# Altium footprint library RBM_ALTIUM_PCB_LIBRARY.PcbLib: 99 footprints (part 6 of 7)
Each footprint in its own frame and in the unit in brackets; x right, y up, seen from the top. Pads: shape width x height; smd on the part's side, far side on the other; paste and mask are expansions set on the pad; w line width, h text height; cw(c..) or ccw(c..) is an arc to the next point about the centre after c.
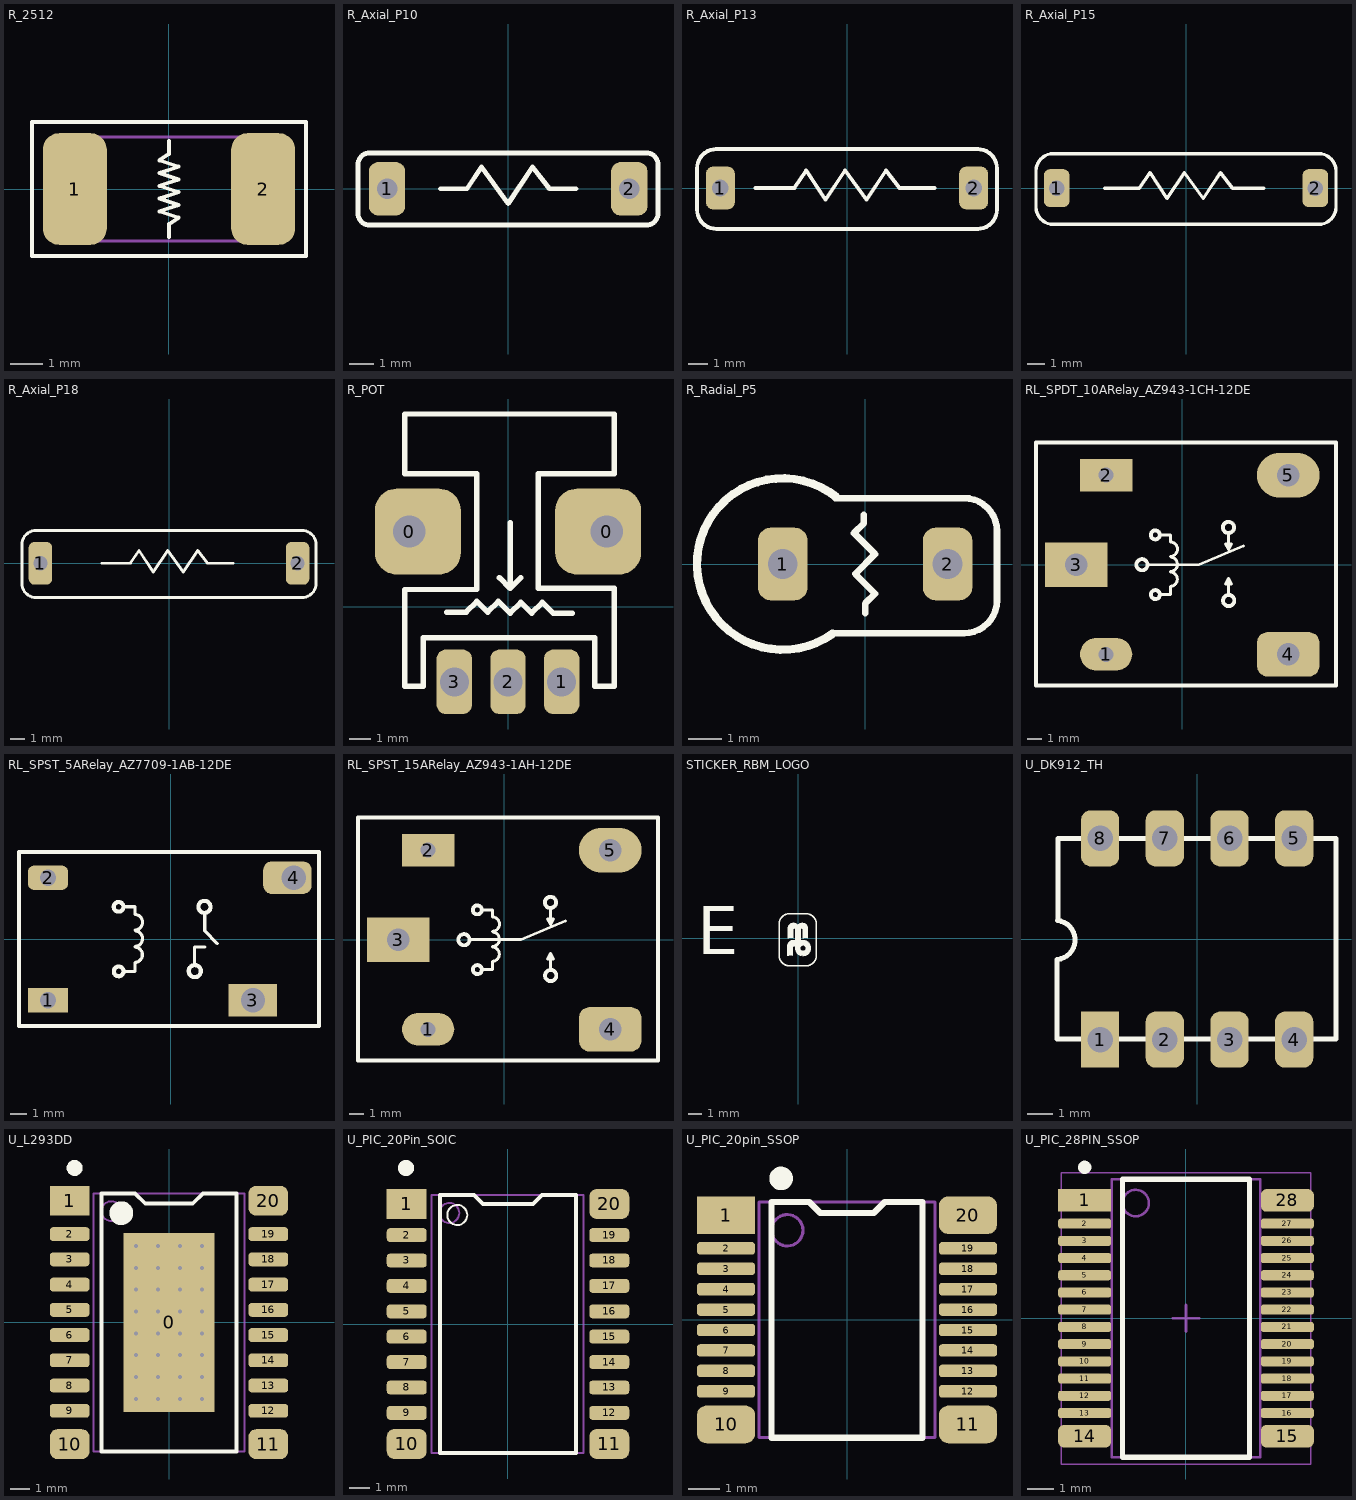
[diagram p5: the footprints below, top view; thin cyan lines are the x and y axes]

## R_2512 [mm] "Chip Resistor, 2-Leads, Body 6.35x3.10mm, IPC Medium Density"
height 0.65
pads (2):
  rrect50% 2x3.5 smd: 1(-2.95,0) 2(2.95,0)
Top Overlay:
  lines w0.125: 0,-1.5 0,-1.1 0.3,-0.9 -0.3,-0.7 0.3,-0.5 -0.3,-0.3 0.3,-0.1 -0.3,0.1 0.3,0.3 -0.3,0.5 0.3,0.7 -0.3,0.9 0,1.1 0,1.5 ; -4.3,-2.1 4.3,-2.1 4.3,2.1 -4.3,2.1 -4.3,-2.1
Mechanical 13:
  lines w0.1: -3.275,-1.625 3.275,-1.625 3.275,1.625 -3.275,1.625 -3.275,-1.625
3D body "R_2512.step": height 0.65, standoff 0, extent -3.275,-1.625 3.275,1.625

## R_Axial_P10 [mm] "Resistors 7mm Length"
pads (2):
  rrect50% 1.5x2.2 hole 0.85: 1(-5,0) 2(5,0)
Top Overlay:
  lines w0.2: -2.8,0 -1.7,0 -1.1,0.9 0,-0.6 1,0.9 1.7,0 2.8,0 ; -6.2,-1.017 ccw(c-5.717,-1.017) -5.717,-1.5 5.7,-1.5 ccw(c5.7,-1.017) 6.183,-1.017 6.183,1 ccw(c5.7,1) 5.7,1.483 -5.717,1.483 ccw(c-5.717,1) -6.2,1 -6.2,-1.017
3D body "User Library-Res40-Axial 0_25W-2_2R.step": height 2.41, standoff -2, extent -5.38,-1.2 5.38,1.2

## R_Axial_P13 [mm] "Resistors 10.5mm Length"
pads (2):
  rrect50% 1.5x2.2 hole 0.85: 1(-6.5,0) 2(6.5,0)
Top Overlay:
  lines w0.2: -6.725,2 6.725,2 ; -6.7,2 ccw(c-6.7,1) -7.7,1 -7.7,-1.1 ccw(c-6.7,-1.1) -6.7,-2.1 6.725,-2.1 ; -4.7,0 -2.7,0 -2.1,0.9 -1.1,-0.6 -0.1,0.9 1,-0.6 2,0.9 2.7,0 4.5,0 ; 6.7,-2.1 ccw(c6.7,-1.1) 7.7,-1.1 7.7,1 ccw(c6.7,1) 6.7,2
3D body "User Library-Res50-Axial 0_5W-2_2K.step": height 5.87, standoff -3.5, extent -6.725,-1.875 6.725,1.875

## R_Axial_P15 [mm] "Resistors 12mm Length"
pads (2):
  rrect50% 1.5x2.2 hole 0.9: 1(-7.5,0) 2(7.5,0)
Top Overlay:
  lines w0.2: -4.7,0 -2.7,0 -2.1,0.9 -1.1,-0.6 -0.1,0.9 1,-0.6 2,0.9 2.7,0 4.5,0 ; -8.7,-1.1 ccw(c-7.7,-1.1) -7.7,-2.1 7.7,-2.1 ccw(c7.7,-1.1) 8.7,-1.1 8.7,1 ccw(c7.7,1) 7.7,2 -7.7,2 ccw(c-7.7,1) -8.7,1 -8.7,-1.1
3D body "User Library-Res50-Axial 0_5W-2_2K.step": height 5.87, standoff -3.5, extent -6.725,-1.875 6.725,1.875

## R_Axial_P18 [mm] "220 ohm 2W 5%"
pads (2):
  rrect50% 1.65x3 hole 1: 1(-9,0) 2(9,0)
Top Overlay:
  lines w0.2: -4.7,0 -2.7,0 -2.1,0.9 -1.1,-0.6 -0.1,0.9 1,-0.6 2,0.9 2.7,0 4.5,0 ; -10.3,-1.4 ccw(c-9.3,-1.4) -9.3,-2.4 9.3,-2.4 ccw(c9.3,-1.4) 10.3,-1.4 10.3,1.3 ccw(c9.3,1.3) 9.3,2.3 -9.3,2.3 ccw(c-9.3,1.3) -10.3,1.3 -10.3,-1.4

## R_POT [mm]
pads (5):
  rrect50% 4x4 hole 1.5 square copper offset 0.4,0: 0(-4.6,3.5)
  rrect50% 4x4 hole 1.5 square copper offset -0.4,0: 0(4.6,3.5)
  rrect50% 1.65x3 hole 1.35: 1(2.5,-3.5) 2(0,-3.5) 3(-2.5,-3.5)
Top Overlay:
  lines w0.254: -2.85,-0.25 -1.95,-0.25 -1.45,0.25 ; -0.4,1.35 0.1,0.85 ; 0.05,-0.25 -0.45,0.25 ; 0.1,3.9 0.1,0.85 ; 0.6,1.35 0.1,0.85 ; 3,-0.3 2.1,-0.3 1.6,0.2 1.1,-0.3 ; -1.45,0.25 -1.45,0.25 ; -1.45,0.25 -0.95,-0.25 -0.45,0.25 ; -0.45,0.25 -0.45,0.25 ; 0.1,-0.3 0.1,-0.3 ; 0.1,-0.3 0.6,0.2 1.1,-0.3 ; 1.1,-0.3 1.1,-0.3 ; -4.8,-3.7 -4.8,0.8 -1.45,0.8 -1.45,6.2 -4.8,6.2 -4.8,8.975 4.952,8.975 4.952,6.2 1.4,6.2 1.4,0.85 4.952,0.85 4.952,-3.7 4.05,-3.7 4.05,-1.45 -3.95,-1.45 -3.95,-3.7 -4.8,-3.7
3D body "SW3dPS-Potentiometer 250U.STEP": height 15.26, standoff -3.8, extent -4.876,-3.8 4.876,8.75

## R_Radial_P5 [mm] "All Through Hole Resistors"
pads (2):
  rrect50% 1.5x2.2 hole 0.9: 1(-2.5,0) 2(2.5,0)
Top Overlay:
  lines w0.2: -1,-2.1 3,-2.1 ccw(c3,-1.1) 4,-1.1 4,1 ccw(c3,1) 3,2 -0.9,2 ; -0.038,1.5 -0.038,1.238 -0.337,0.938 0.3,0.3 ; 0,-1.5 0,-1.2 0.3,-0.9 -0.3,-0.3 ; -0.3,-0.3 0.3,0.3 ; -0.3,-0.3 -0.3,-0.3 ; 0.3,0.3 0.3,0.3
  lines w0.254: -0.989,-2.116 cw(c-2.5,0) -0.876,2.03
3D body "Res_Radial_5mmP.STEP": height 15.25, standoff -3, extent -5,-2.5 2.75,2.5

## RL_SPDT_10ARelay_AZ943-1CH-12DE [mm]
pads (5):
  oval 3.5x2.2 hole 1: 1(-5.1,-6)
  rect 3.5x2.2 hole 1: 2(-5.1,6)
  rect 4.2x3 hole 1.5: 3(-7.1,0)
  rrect50% 4.2x3 hole 1.5: 4(7.1,-6)
  oval 4.2x3 hole 1.5: 5(7.1,6)
Top Overlay:
  circle w0.254: c-1.8,-2.001 r0.3
  circle w0.254: c-1.804,2 r0.3
  circle w0.254: c3.111,-2.4 r0.376
  circle w0.254: c3.096,2.5 r0.376
  circle w0.254: c-2.704,0 r0.376
  lines w0.2: -2.329,0 1.096,0 4.109,1.268 ; -1.429,2 -0.789,2 -0.789,1.534 ; -1.424,-2.001 -0.784,-2.001 ; -0.791,-1.444 ccw(c-0.81,-0.968) -0.789,-0.492 ; -0.79,-0.458 ccw(c-0.81,0.028) -0.747,0.511 ; -0.79,0.559 ccw(c-0.81,1.046) -0.789,1.533 ; -0.789,-1.986 -0.789,-1.477 ; 3.096,-2.039 3.096,-0.906 ; 3.111,2.139 3.111,1.006 ; 2.896,1.4 3.111,1.006 ; 2.896,1.4 3.111,1.006 ; 2.896,1.4 3.111,1.4 ; 3.096,-1.3 3.311,-1.3 ; 3.096,-1.3 3.096,-0.906 ; 3.096,-1.3 2.896,-1.3 3.096,-0.906 ; 3.096,-0.906 3.311,-1.3 ; 3.096,-0.906 3.311,-1.3 ; 3.111,1.006 3.111,1.4 ; 3.111,1.006 3.311,1.4 3.111,1.4
  lines w0.254: -9.8,8.2 -9.8,-8.1 10.3,-8.1 10.3,8.2 -9.7,8.2
3D body: height 3, standoff -4, extent -5.348,-6.249 -4.85,-5.75
3D body: height 3, standoff -4, extent -7.695,-0.599 -6.5,0.599
3D body: height 3, standoff -4, extent -5.348,5.751 -4.85,6.25
3D body: height 3, standoff -4, extent 6.505,5.401 7.7,6.599
3D body: height 3, standoff -4, extent 6.505,-6.599 7.7,-5.401
3D body: height 15, standoff 0.56, extent -9.8,-8.1 10.3,8.2

## RL_SPST_5ARelay_AZ7709-1AB-12DE [mm]
pads (4):
  rect 2.5x1.5 hole 1: 1(-7.62,-3.8)
  rrect50% 2.5x1.5 hole 1: 2(-7.62,3.8)
  rect 3x2 hole 1.5: 3(5.08,-3.8)
  rrect50% 3x2 hole 1.5 copper offset -0.4,0: 4(7.62,3.8)
Top Overlay:
  circle w0.254: c-3.244,1.993 r0.3
  circle w0.254: c-3.24,-2.008 r0.3
  circle w0.254: c1.48,-1.993 r0.376
  circle w0.254: c2.08,1.993 r0.376
  lines w0.2: -2.869,1.993 -2.229,1.993 -2.229,1.526 ; -2.865,-2.008 -2.225,-2.008 ; -2.231,-1.451 ccw(c-2.25,-0.975) -2.229,-0.499 ; -2.231,-0.466 ccw(c-2.25,0.021) -2.187,0.504 ; -2.231,0.552 ccw(c-2.25,1.039) -2.229,1.525 ; -2.229,-1.993 -2.229,-1.484 ; 1.465,-1.632 1.465,-0.499 2.095,-0.499 ; 2.095,1.631 2.095,0.499 2.88,-0.286
  lines w0.254: -9.42,-5.4 9.18,-5.4 9.18,5.4 -9.42,5.4 -9.42,-5.4
3D body: height 15.5, standoff 0.56, extent -9.42,-5.4 9.18,5.4
3D body: height 3, standoff -4, extent 7.025,3.201 8.22,4.399
3D body: height 3, standoff -4, extent -7.868,3.551 -7.37,4.05
3D body: height 3, standoff -4, extent 4.485,-4.399 5.68,-3.201
3D body: height 3, standoff -4, extent -7.868,-4.049 -7.37,-3.55

## RL_SPST_15ARelay_AZ943-1AH-12DE [mm]
pads (5):
  oval 3.5x2.2 hole 1: 1(-5.1,-6)
  rect 3.5x2.2 hole 1: 2(-5.1,6)
  rect 4.2x3 hole 1.5: 3(-7.1,0)
  rrect50% 4.2x3 hole 1.5: 4(7.1,-6)
  oval 4.2x3 hole 1.5: 5(7.1,6)
Top Overlay:
  circle w0.254: c-1.8,-2 r0.3
  circle w0.254: c-1.804,2.001 r0.3
  circle w0.254: c3.111,-2.399 r0.376
  circle w0.254: c3.096,2.501 r0.376
  circle w0.254: c-2.704,0.001 r0.376
  lines w0.2: -2.329,0.001 1.096,0.001 4.109,1.269 ; -1.429,2.001 -0.789,2.001 -0.789,1.535 cw(c-0.81,1.047) -0.79,0.56 ; -1.424,-2 -0.784,-2 ; -0.791,-1.443 ccw(c-0.81,-0.967) -0.789,-0.491 ; -0.79,-0.457 ccw(c-0.81,0.029) -0.747,0.512 ; -0.789,-1.985 -0.789,-1.476 ; 3.096,-2.038 3.096,-0.905 ; 3.111,2.14 3.111,1.007 ; 2.896,1.401 3.111,1.007 ; 2.896,1.401 3.111,1.007 ; 2.896,1.401 3.111,1.401 ; 3.096,-1.299 3.311,-1.299 ; 3.096,-1.299 3.096,-0.905 ; 3.096,-1.299 2.896,-1.299 3.096,-0.905 ; 3.096,-0.905 3.311,-1.299 ; 3.096,-0.905 3.311,-1.299 ; 3.111,1.007 3.111,1.401 ; 3.111,1.007 3.311,1.401 3.111,1.401
  lines w0.254: -9.8,8.2 -9.8,-8.1 10.3,-8.1 10.3,8.2 -9.7,8.2
3D body: height 3, standoff -4, extent -5.348,-6.249 -4.85,-5.75
3D body: height 3, standoff -4, extent -7.695,-0.599 -6.5,0.599
3D body: height 3, standoff -4, extent -5.348,5.751 -4.85,6.25
3D body: height 3, standoff -4, extent 6.505,5.401 7.7,6.599
3D body: height 3, standoff -4, extent 6.505,-6.599 7.7,-5.401
3D body: height 15, standoff 0.56, extent -9.8,-8.1 10.3,8.2

## STICKER_RBM_LOGO [mm]
Top Layer:
  region: -3.6,-0.95
  region: -3.6,-0.95
  region: -3.6,-0.95
  region: -3.6,-0.95
  region: 10,1.7
  region: 10,1.7
  region: 10,1.7
  region: 10,1.7
Top Overlay:
  drawing of 2 lines, arcs and shapes, not listed
  text "E" at -7.396,-2.341 h6
Bottom Overlay:
  drawing of 26 lines, arcs and shapes, not listed

## U_DK912_TH [mm]
pads (8):
  rect 1.5x2.2 hole 1: 1(-3.81,-3.95)
  rrect50% 1.5x2.2 hole 1: 2(-1.27,-3.95) 3(1.27,-3.95) 4(3.81,-3.95) 5(3.81,3.95) 6(1.27,3.95) 7(-1.27,3.95) 8(-3.81,3.95)
Top Overlay:
  lines w0.2: -5.5,-0.8 -5.5,-3.92 5.45,-3.92 5.45,3.95 -5.47,3.95 -5.47,0.724 ; -5.471,0.724 cw(c-5.559,-0.038) -5.47,-0.8
3D body "SW3DPS-DIP 8 IC-DEFAULT.STEP": height 5.58, standoff -3, extent -5.47,-3.92 5.45,3.95

## U_L293DD [mm] "SOIC, 20-Leads, Body 12.80x7.50mm, Pitch 1.27mm, Thermal Pad 9.00x4.60mm, IPC Medium Density"
height 2.65
pads (21):
  rect 4.6x9 smd: 0(0,0)
  rect 2x1.5 smd mask+0.3: 1(-5,6.125)
  rrect50% 2x0.7 smd mask+0.3: 2(-5,4.445) 3(-5,3.175) 4(-5,1.905) 5(-5,0.635) 6(-5,-0.635) 7(-5,-1.905) 8(-5,-3.175) 9(-5,-4.445) 12(5,-4.445) 13(5,-3.175) 14(5,-1.905) 15(5,-0.635) 16(5,0.635) 17(5,1.905) 18(5,3.175) 19(5,4.445)
  rrect50% 2x1.5 smd mask+0.3: 10(-5,-6.125) 11(5,-6.125) 20(5,6.125)
via 1.65,-3.85 diameter 0.5 hole 0.2
via 0.55,-3.85 diameter 0.5 hole 0.2
via -0.55,-3.85 diameter 0.5 hole 0.2
via -1.65,-3.85 diameter 0.5 hole 0.2
via 1.65,-2.75 diameter 0.5 hole 0.2
via 0.55,-2.75 diameter 0.5 hole 0.2
via -0.55,-2.75 diameter 0.5 hole 0.2
via -1.65,-2.75 diameter 0.5 hole 0.2
via 1.65,-1.65 diameter 0.5 hole 0.2
via 0.55,-1.65 diameter 0.5 hole 0.2
via -0.55,-1.65 diameter 0.5 hole 0.2
via -1.65,-1.65 diameter 0.5 hole 0.2
via 1.65,-0.55 diameter 0.5 hole 0.2
via 0.55,-0.55 diameter 0.5 hole 0.2
via -0.55,-0.55 diameter 0.5 hole 0.2
via -1.65,-0.55 diameter 0.5 hole 0.2
via 1.65,0.55 diameter 0.5 hole 0.2
via 0.55,0.55 diameter 0.5 hole 0.2
via -0.55,0.55 diameter 0.5 hole 0.2
via -1.65,0.55 diameter 0.5 hole 0.2
via 1.65,1.65 diameter 0.5 hole 0.2
via 0.55,1.65 diameter 0.5 hole 0.2
via -0.55,1.65 diameter 0.5 hole 0.2
via -1.65,1.65 diameter 0.5 hole 0.2
via 1.65,2.75 diameter 0.5 hole 0.2
via 0.55,2.75 diameter 0.5 hole 0.2
via -0.55,2.75 diameter 0.5 hole 0.2
via -1.65,2.75 diameter 0.5 hole 0.2
via 1.65,3.85 diameter 0.5 hole 0.2
via 0.55,3.85 diameter 0.5 hole 0.2
via -0.55,3.85 diameter 0.5 hole 0.2
via -1.65,3.85 diameter 0.5 hole 0.2
Top Overlay:
  circle w0.4: c-4.75,7.775 r0.2
  circle w0.6: c-2.4,5.5 r0.3
  lines w0.2: -3.4,-6.5 3.4,-6.5 3.4,6.5 1.7,6.5 1.175,5.975 -1.175,5.975 -1.7,6.5 -3.4,6.5 -3.4,-6.5
Assembly Top:
  circle w0.1: c-2.9,5.6 r0.5
  lines w0.1: -3.8,-6.5 3.8,-6.5 3.8,6.5 -3.8,6.5 -3.8,-6.5
Courtyard Top:
  lines w0.1: -0.5,0 0.5,0 ; 0,-0.5 0,0.5
3D body "SOIC127P1030X265_HS-21N.step": height 2.65, standoff 0, extent -5.162,-6.5 5.162,6.5

## U_PIC_20Pin_SOIC [mm] "SOIC, 20-Leads, Body 12.80x7.50mm, Pitch 1.27mm, IPC Medium Density"
height 2.65
pads (20):
  rect 2x1.5 smd mask+0.3: 1(-5.063,6)
  rrect50% 2x0.7 smd mask+0.3: 2(-5.063,4.445) 3(-5.063,3.175) 4(-5.063,1.905) 5(-5.063,0.635) 6(-5.063,-0.635) 7(-5.063,-1.905) 8(-5.063,-3.175) 9(-5.063,-4.445) 12(5.063,-4.445) 13(5.063,-3.175) 14(5.063,-1.905) 15(5.063,-0.635) 16(5.063,0.635) 17(5.063,1.905) 18(5.063,3.175) 19(5.063,4.445)
  rrect50% 2x1.5 smd mask+0.3: 10(-5.063,-6) 11(5.063,-6)
  rrect50% 2x1.5 smd paste+0 mask+0.3: 20(5.063,6)
Top Overlay:
  circle w0.4: c-5.1,7.8 r0.2
  circle w0.1: c-2.537,5.45 r0.5
  lines w0.2: -3.4,-6.45 -3.4,6.45 -1.7,6.45 -1.25,6 1.25,6 1.7,6.45 3.4,6.45 3.4,-6.45 -3.4,-6.45
Mechanical 13:
  circle w0.1: c-2.937,5.55 r0.5
  lines w0.1: -3.837,-6.45 -3.837,6.45 3.763,6.45 3.763,-6.45 -3.837,-6.45
3D body "SOIC127P1020X265-20N.step": height 2.65, standoff 0, extent -5.062,-6.425 5.088,6.475

## U_PIC_20pin_SSOP [mm] "SOP, 20-Leads, Body 7.20x5.30mm, Pitch 0.65mm, IPC Medium Density"
height 2
pads (20):
  rect 1.85x1.2 smd mask+0.2: 1(-3.85,3.33)
  rrect50% 1.85x0.395 smd mask+0.2: 2(-3.85,2.275) 3(-3.85,1.625) 4(-3.85,0.975) 5(-3.85,0.325) 6(-3.85,-0.325) 7(-3.85,-0.975) 8(-3.85,-1.625) 9(-3.85,-2.275) 12(3.85,-2.275) 13(3.85,-1.625) 14(3.85,-0.975) 15(3.85,-0.325) 16(3.85,0.325) 17(3.85,0.975) 18(3.85,1.625) 19(3.85,2.275)
  rrect50% 1.85x1.2 smd mask+0.2: 10(-3.85,-3.33) 11(3.85,-3.33) 20(3.85,3.33)
Top Overlay:
  circle w0.5: c-2.1,4.5 r0.125
  lines w0.2: -2.4,-3.75 2.4,-3.75 2.4,3.75 1.2,3.75 0.85,3.4 -0.85,3.4 -1.2,3.75 -2.4,3.75 -2.4,-3.75
Mechanical 13:
  circle w0.1: c-1.9,2.85 r0.5
  lines w0.1: -2.8,-3.75 2.8,-3.75 2.8,3.75 -2.8,3.75 -2.8,-3.75
3D body "SOP65P780X200-20N.step": height 2, standoff 0, extent -3.9,-3.75 3.9,3.75

## U_PIC_28PIN_SSOP [mm] "SOP, 28-Leads, Body 10.20x5.30mm, Pitch 0.65mm, Thermal Pad 8.00x4.00mm, IPC Medium Density"
height 2
pads (28):
  rect 2x0.85 smd mask+0.2: 1(-3.825,4.45)
  rrect50% 2x0.38 smd mask+0.2: 2(-3.825,3.575) 3(-3.825,2.925) 4(-3.825,2.275) 5(-3.825,1.625) 6(-3.825,0.975) 7(-3.825,0.325) 8(-3.825,-0.325) 9(-3.825,-0.975) 10(-3.825,-1.625) 11(-3.825,-2.275) 12(-3.825,-2.925) 13(-3.825,-3.575) 16(3.825,-3.575) 17(3.825,-2.925) 18(3.825,-2.275) 19(3.825,-1.625) 20(3.825,-0.975) 21(3.825,-0.325) 22(3.825,0.325) 23(3.825,0.975) 24(3.825,1.625) 25(3.825,2.275) 26(3.825,2.925) 27(3.825,3.575)
  rrect50% 2x0.85 smd mask+0.2: 14(-3.825,-4.45) 15(3.825,-4.45) 28(3.825,4.45)
Top Overlay:
  circle w0.25: c-3.825,5.7 r0.125
  lines w0.2: -2.4,-5.25 2.4,-5.25 2.4,5.25 -2.4,5.25 -2.4,-5.25
Assembly Top:
  circle w0.1: c-1.9,4.35 r0.5
  lines w0.1: -2.8,-5.25 2.8,-5.25 2.8,5.25 -2.8,5.25 -2.8,-5.25
Courtyard Top:
  lines w0.05: -4.7,-5.5 4.7,-5.5 4.7,5.5 -4.7,5.5 -4.7,-5.5
  lines w0.1: -0.5,0 0.5,0 ; 0,-0.5 0,0.5
3D body "U_PIC16F18856_SSOP.step": height 2, standoff 0, extent -3.9,-5.25 3.9,5.25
